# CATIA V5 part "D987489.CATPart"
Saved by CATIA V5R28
Part number: 2020001L001-MBS
Revision: -
Definition: D987489
Nomenclature: CPLM TEST - INTEGRATION
Publications: "SegmentExtremity.171", "SegmentExtremity.172", "ElecLogTerm.88", "Flexible Curve.48", "Point.3059", "BCP.10", "SegmentExtremity.249", "SegmentExtremity.250", "ElecLogTerm.123", "Flexible Curve.62", "Point.4776", "SegmentExtremity.253", "SegmentExtremity.254", "ElecLogTerm.125", "Flexible Curve.63", "SegmentExtremity.259", "SegmentExtremity.260", "ElecLogTerm.128", "Point.4867", "SegmentExtremity.267", "SegmentExtremity.268", "ElecLogTerm.132", "Flexible Curve.66", "BCP.13", "Point.4920", "SegmentExtremity.287", "SegmentExtremity.288", "ElecLogTerm.142", "Flexible Curve.71", "BCP.4", "SegmentExtremity.289", "SegmentExtremity.290", "ElecLogTerm.144", "Point.5190", "BCP.11", "BCP.17", "Flexible Curve.75", "SegmentExtremity.301", "SegmentExtremity.302", "ElecLogTerm.150", "SegmentExtremity.303", "SegmentExtremity.304", "ElecLogTerm.151", "SegmentExtremity.305", "SegmentExtremity.306", "ElecLogTerm.152", "Point.6389", "SegmentExtremity.307", "SegmentExtremity.308", "ElecLogTerm.153", "Flexible Curve.76", "BCP.1", "SegmentExtremity.309", "SegmentExtremity.310", "ElecLogTerm.154", "Point.6393", "SegmentExtremity.311", "SegmentExtremity.312", "ElecLogTerm.155", "Flexible Curve.77", "BCP.2", "Point.6397", "Point.6397.1"
Bounding box of the stored display mesh (mm): x 24778.801 to 25364.719, y -496.829 to 562.984, z 2246.238 to 3196.481
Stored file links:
  C:\Users\u305772\OneDrive - Gulfstream Aerospace\AD PAG\Harness\D987489.CATPart
  C:\Users\u305772\OneDrive - Gulfstream Aerospace\AD PAG\Harness\D987488.CATProduct
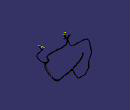
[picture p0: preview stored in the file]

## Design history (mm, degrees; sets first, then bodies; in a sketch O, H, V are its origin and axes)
ElecProtectionSet1
TTRSSet1
ElecRouteBody1
EhiBundleSegmentBody1 "W72001-R4"
ElecRouteBody2
EhiBundleSegmentBody2 "W72001-R6"
ElecRouteBody3
EhiBundleSegmentBody3 "W72001-R2"
EhiBundleSegmentBody4 "W72001-R3"
ElecRouteBody4
EhiBundleSegmentBody5 "W72001-X11"
ElecRouteBody5
EhiBundleSegmentBody6 "W72001-X5"
EhiBundleSegmentBody7 "W72001-R1"
ElecRouteBody6
EhiBundleSegmentBody8 "W72001-R7"
EhiBundleSegmentBody9 "W72001-R8"
f4a2d38f3ddc11d3a929006094b99c4b_11 "CATTPSSet"
EhiBundleSegmentBody10 "W72001-R12"
ElecRouteBody7
EhiBundleSegmentBody11 "W72001-X13"
EhiBundleSegmentBody12 "W72001-R9"
ElecRouteBody8
EhiBundleSegmentBody13 "W72001-R10"
Set1
  Point1: linked copy from another document
  DatumSurface1: linked copy from another document
  Point2 "BCP": linked copy from another document
  Point3 "BCP": linked copy from another document
  DatumSurface2: linked copy from another document
  Point4 "BCP": linked copy from another document
  DatumSurface3: linked copy from another document
  Point5 "BCP": linked copy from another document
  DatumSurface4: linked copy from another document
  Point6 "BCP": linked copy from another document
  DatumSurface5: linked copy from another document
  Point7 "BCP": linked copy from another document
  DatumSurface6: linked copy from another document
  Point8 "BCP": linked copy from another document
  DatumSurface7: linked copy from another document
  DatumSurface8: linked copy from another document
Set2
  Point9: type OnCurve, RefPoint Point5, Length 177.8
  Plane1 "A091685.29846548475648465!EHISUPPORT-RefPlane1.1": stored without definition
  Plane2 "A091685.29846548475648465!EHISUPPORT-RefPlane2": stored without definition
  Point10 "A091685.29846548475648465!EHISUPPORT-RefPoint1": stored without definition
  Point11: type OnPlane, Support Plane1, RefPoint Point10, X 0, Y 0, Direction (-0.012, 0.9999, 0)
  Project1: ToProject Point11, Support Plane2
  Point12: type OnPlane, Support Plane1, RefPoint Point10, X 0, Y 0, Direction (-0.012, 0.9999, 0)
  Project2: ToProject Point12, Support Plane2
  Plane3 "AS21919WDG08.24!EHISUPPORT-RefPlane1.1": stored without definition
  Plane4 "AS21919WDG08.24!EHISUPPORT-RefPlane2": stored without definition
  Point13 "AS21919WDG08.24!EHISUPPORT-RefPoint1": stored without definition
  Point14: type OnPlane, Support Plane3, RefPoint Point13, X 0, Y 0, Direction (-1, -0.0058, 0)
  Project3: ToProject Point14, Support Plane4
  Plane5: stored without definition
  Plane6: stored without definition
  Point15: stored without definition
  Point16: type OnPlane, Support Plane5, RefPoint Point15, X 0, Y 0, Direction (0, -1, 0)
  Project4: ToProject Point16, Support Plane6
  Plane7: stored without definition
  Plane8: stored without definition
  Point17: stored without definition
  Point18: type OnPlane, Support Plane7, RefPoint Point17, X 0, Y 0, Direction (-0.02, -0.9998, 0)
  Project5: ToProject Point18, Support Plane8
  Plane9: stored without definition
  Plane10: stored without definition
  Point19: stored without definition
  Point20: type OnPlane, Support Plane9, RefPoint Point19, X 0, Y 0, Direction (0.9997, 0.026, 0)
  Project6: ToProject Point20, Support Plane10
  Plane11: stored without definition
  Plane12: stored without definition
  Point21: stored without definition
  Point22: type OnPlane, Support Plane11, RefPoint Point21, X 0, Y 0, Direction (1, -0.0029, 0)
  Project7: ToProject Point22, Support Plane12
  Plane13: stored without definition
  Plane14: stored without definition
  Point23: stored without definition
  Point24: type OnPlane, Support Plane13, RefPoint Point23, X 0, Y 0, Direction (0.9999, 0.0104, 0)
  Project8: ToProject Point24, Support Plane14
  Plane15: stored without definition
  Plane16: stored without definition
  Point25: stored without definition
  Point26: type OnPlane, Support Plane15, RefPoint Point25, X 0, Y 0, Direction (0.9998, -0.0192, 0)
  Project9: ToProject Point26, Support Plane16
  Plane17: stored without definition
  Plane18: stored without definition
  Point27: stored without definition
  Point28: type OnPlane, Support Plane17, RefPoint Point27, X 0, Y 0, Direction (0.9862, 0.1656, 0)
  Project10: ToProject Point28, Support Plane18
  Plane19: stored without definition
  Plane20: stored without definition
  Point29: stored without definition
  Point30: type OnPlane, Support Plane19, RefPoint Point29, X 0, Y 0, Direction (-0.9601, 0.2795, 0)
  Project11: ToProject Point30, Support Plane20
  Plane21: stored without definition
  Plane22: stored without definition
  Point31: stored without definition
  Point32: type OnPlane, Support Plane21, RefPoint Point31, X 0, Y 0, Direction (-0.999, 0.0452, 0)
  Project12: ToProject Point32, Support Plane22
  Plane23: stored without definition
  Plane24: stored without definition
  Point33: stored without definition
  Point34: type OnPlane, Support Plane23, RefPoint Point33, X 0, Y 0, Direction (0, -1, 0)
  Project13: ToProject Point34, Support Plane24
  Plane25 "AS21919WDG12.20130920105739_54385!EHISUPPORT-RefPlane1.1": stored without definition
  Plane26 "AS21919WDG12.20130920105739_54385!EHISUPPORT-RefPlane2": stored without definition
  Point35 "AS21919WDG12.20130920105739_54385!EHISUPPORT-RefPoint1": stored without definition
  Point36: type OnPlane, Support Plane25, RefPoint Point35, X 0, Y 0, Direction (0, 1, 0)
  Project14: ToProject Point36, Support Plane26
  Point37: type OnPlane, Support Plane25, RefPoint Point35, X 0, Y 0, Direction (0, 1, 0)
  Project15: ToProject Point37, Support Plane26
  Point38: type OnPlane, Support Plane25, RefPoint Point35, X 0, Y 0, Direction (0, 1, 0)
  Project16: ToProject Point38, Support Plane26
  Plane27 "AS21919WDG13.20130920105743_88468!EHISUPPORT-RefPlane1.1": stored without definition
  Plane28 "AS21919WDG13.20130920105743_88468!EHISUPPORT-RefPlane2": stored without definition
  Point39 "AS21919WDG13.20130920105743_88468!EHISUPPORT-RefPoint1": stored without definition
  Point40: type OnPlane, Support Plane27, RefPoint Point39, X 0, Y 0, Direction (0, -1, 0)
  Project17: ToProject Point40, Support Plane28
  Point41: (25061.3326, 424.8483, 3026.4991)
  Point42: (25108.936, 227.3627, 2365.449)
Set3
  Point43: stored without definition
  Point44: type OnCurve, RefPoint Project14, Length 101.6
  Point45: type OnCurve, RefPoint Project5, LENGTH 76.2
  Plane29 "A091689.589715!EHISUPPORT-RefPlane1.1": stored without definition
  Plane30 "A091689.589715!EHISUPPORT-RefPlane2": stored without definition
  Point46 "A091689.589715!EHISUPPORT-RefPoint1": stored without definition
  Point47: type OnPlane, Support Plane29, RefPoint Point46, X 0, Y 0, Direction (0.0013, -1, 0)
  Project18: ToProject Point47, Support Plane30
Set4
  Point48: type OnCurve, RefPoint Point3, Length 101.6
  Point49: type OnCurve, RefPoint Point4, Length 127
  Point50: (24911.8269, 237.3215, 2599.3216)
Body1 (main body)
